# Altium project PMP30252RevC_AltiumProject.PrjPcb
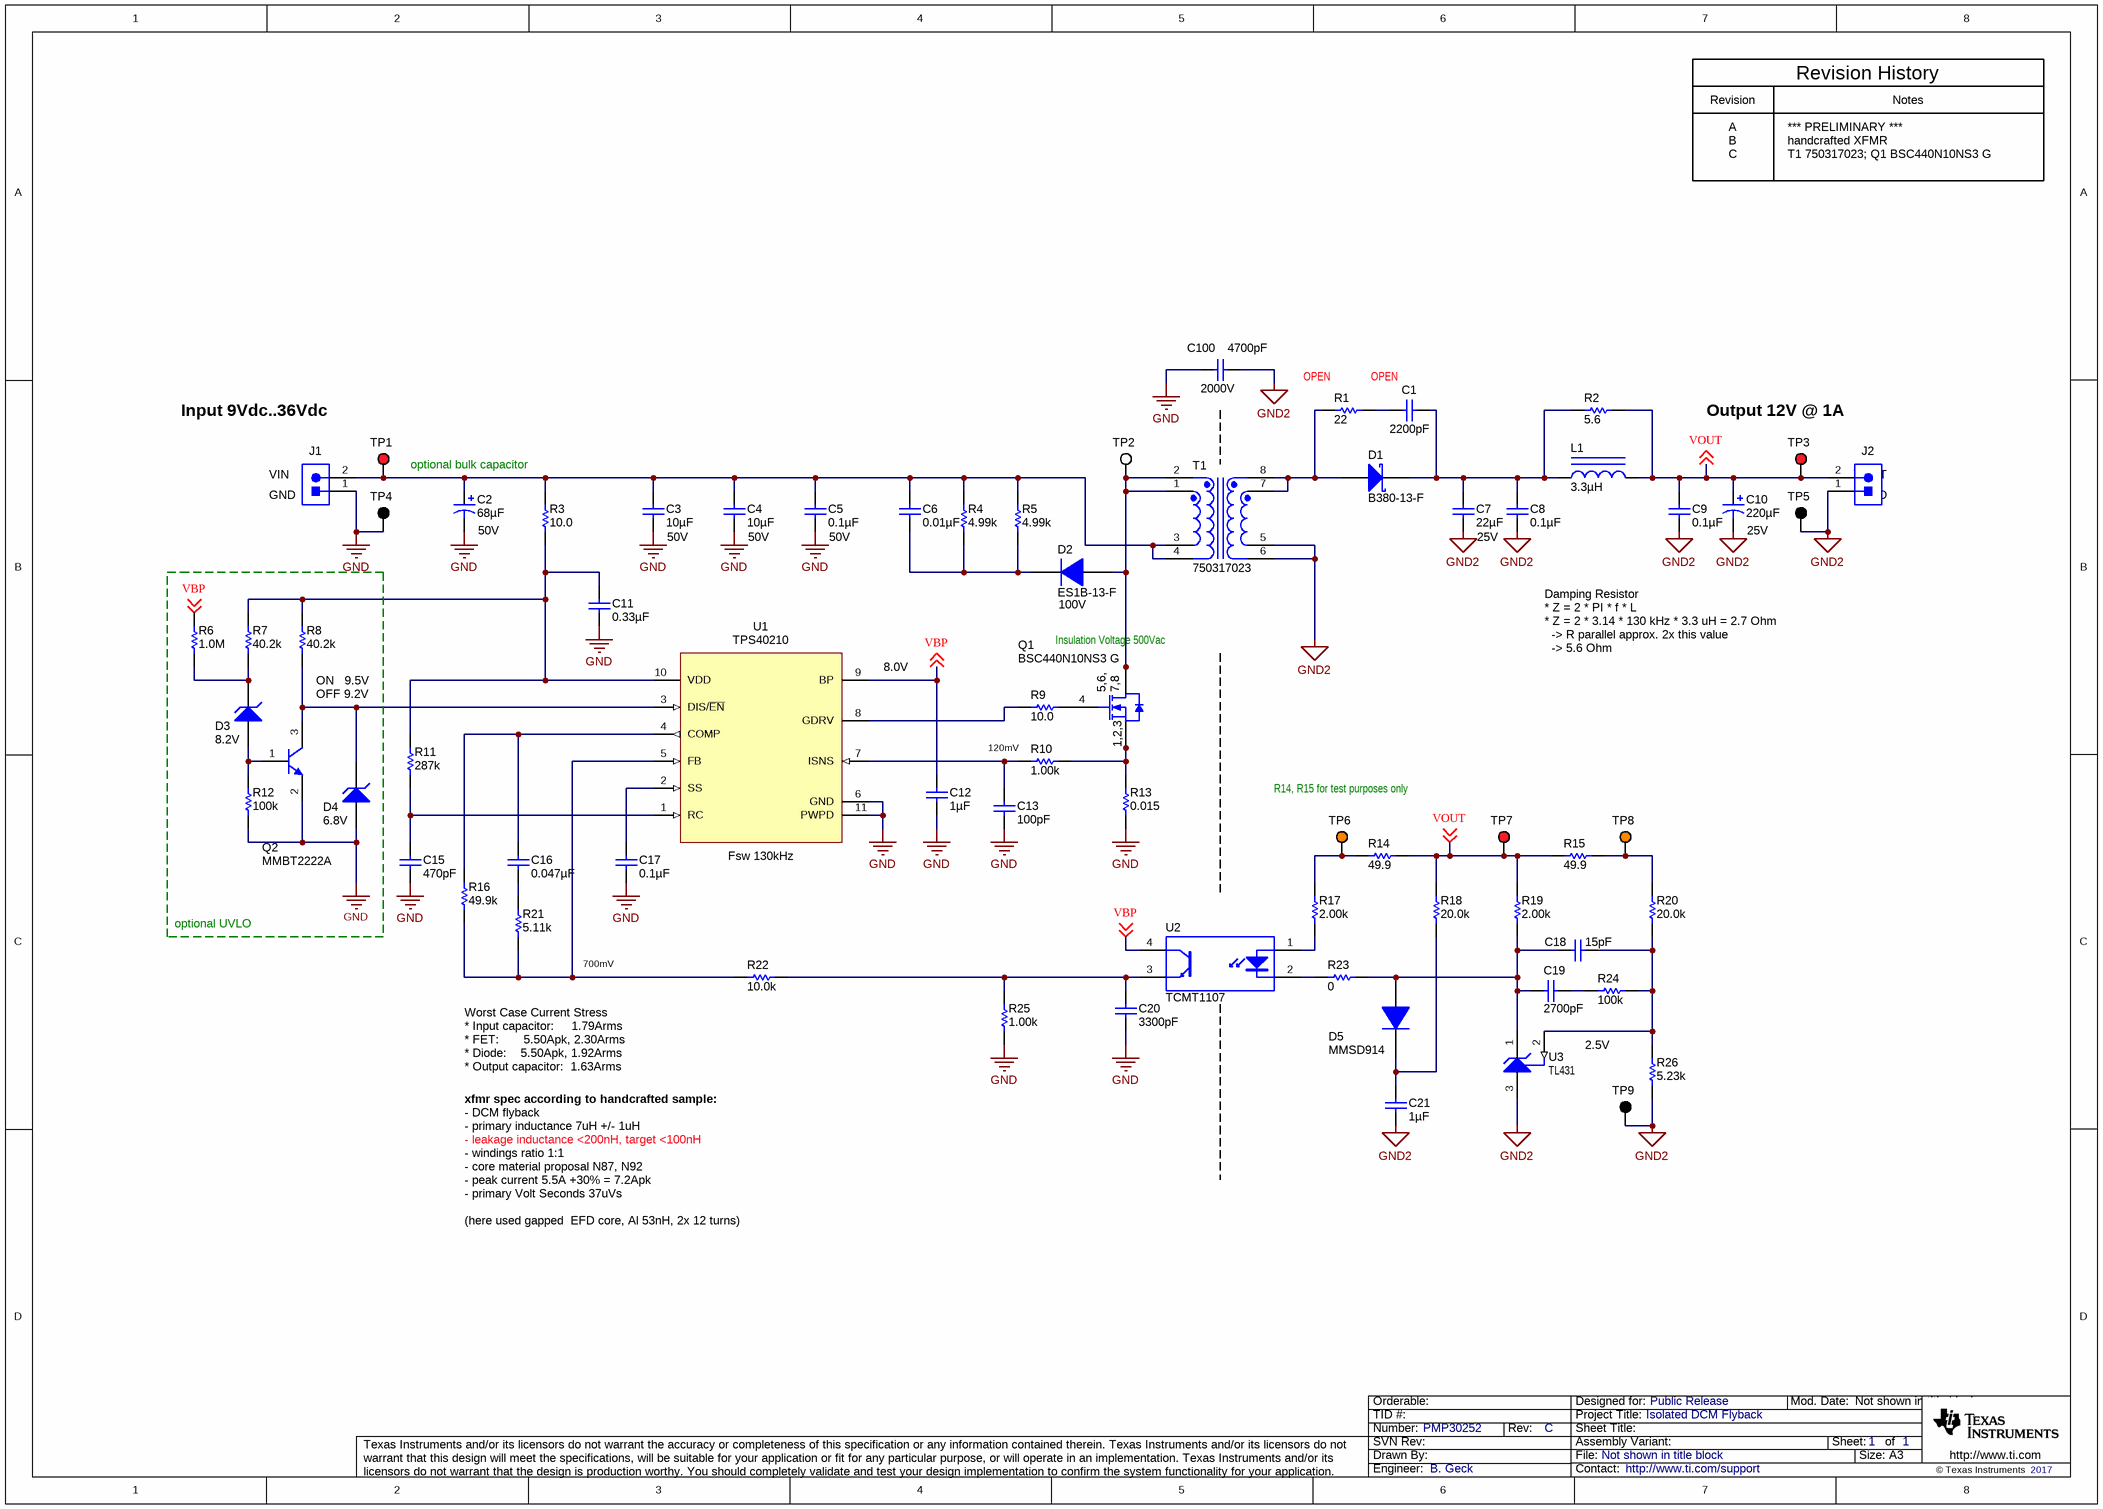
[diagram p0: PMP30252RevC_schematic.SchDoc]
CopyrightYear: 2017; PCB_Layout: B. Geck; PCB_Rev: A; PRJ_Customer: Public Release; PRJ_Engineer: B. Geck; PRJ_Number: PMP30252; PRJ_Title: Isolated DCM Flyback; SCH_Rev: C; TechSupport: http://www.ti.com/support
1 sheet, 70 parts. Net scope: global (net labels, ports and power ports of the same name join across sheets).
Board file: PMP30252RevA.PcbDoc

## Sheet PMP30252RevC_schematic.SchDoc
size A3; Date: Not shown in title block; ApprovedBy: Not shown in title block; CheckedBy: Not shown in title block; Author: Not shown in title block; CompanyName: Not shown in title block; Engineer: Not shown in title block; Organization: Not shown in title block; Address1: Not shown in title block; Address2: Not shown in title block; Address3: Not shown in title block; Address4: Not shown in title block; DocumentNumber: 1; Revision: Use project parameter SCH_Rev; SheetNumber: 1; SheetTotal: 1; PageSetup: Record=PageOptions¦CenterHorizontal=True¦CenterVertical=True¦PrintScale=0.68¦XCorrection=1.00¦YCorrection=1.00¦PrintKind=0¦BorderSize=5000000¦LeftOffset=0¦BottomOffset=0¦Orientation=2¦PaperLength=1000¦PaperWidth=1000¦Scale=100¦PaperSource=15¦PrintQuality=600¦MediaType=1¦DitherType=10¦PrintScaleMode=1¦PaperKind=A4¦PaperIndex=9

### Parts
C1  ValueDisplayed: 2200pF  [0603]  (hidden comment: GRM188R72A222KA01D)
C2  ValueDisplayed: 68µF  Value2: 50V  [SM_RADIAL_8MM]  (hidden comment: EEHZC1H680P)
C3  ValueDisplayed: 10µF  Value2: 50V  [1210_270]  (hidden comment: GRM32ER71H106KA12L)
C4  ValueDisplayed: 10µF  Value2: 50V  [1210_270]  (hidden comment: GRM32ER71H106KA12L)
C5  ValueDisplayed: 0.1µF  Value2: 50V  [0603]  (hidden comment: GCM188R71H104KA57D)
C6  ValueDisplayed: 0.01µF  [0805_HV]  (hidden comment: GRM21BR72A103MA01L)
C7  ValueDisplayed: 22µF  Value2: 25V  [1210_270]  (hidden comment: GRM32ER71E226KE15L)
C8  ValueDisplayed: 0.1µF  [0603]  (hidden comment: GCM188R71H104KA57D)
C9  ValueDisplayed: 0.1µF  [0603]  (hidden comment: GCM188R71H104KA57D)
C10  ValueDisplayed: 220µF  Value2: 25V  [SM_RADIAL_8MM]  (hidden comment: EEHZC1E221P)
C11  ValueDisplayed: 0.33µF  [0805_HV]  (hidden comment: GRM219R71H334KA88D)
C12  ValueDisplayed: 1µF  [0603]  (hidden comment: GRM188R71C105KA12D)
C13  ValueDisplayed: 100pF  [0603]  (hidden comment: GRM1885C1H101JA01D)
C15  ValueDisplayed: 470pF  [0603]  (hidden comment: GRM1885C1H471JA01D)
C16  ValueDisplayed: 0.047µF  [0603]  (hidden comment: GRM188R71E473KA01D)
C17  ValueDisplayed: 0.1µF  [0603]  (hidden comment: GCM188R71H104KA57D)
C18  ValueDisplayed: 15pF  [0603]  (hidden comment: GRM1885C1H150JA01D)
C19  ValueDisplayed: 2700pF  [0603]  (hidden comment: GRM188R71E272KA01D)
C20  ValueDisplayed: 3300pF  [0603]  (hidden comment: GRM188R71H332KA01D)
C21  ValueDisplayed: 1µF  [0603]  (hidden comment: GRM188R71C105KA12D)
C100  ValueDisplayed: 4700pF  Value2: 2000V  [1812]  (hidden comment: 1812GC472KA1)
D1  B380-13-F  [SMC]
D2  ES1B-13-F  value 100V  [SMA]
D3  value 8.2V  [SOD-323]  (hidden comment: MMSZ5237BS-7-F)
D4  value 6.8V  [sod-323]  (hidden comment: MMSZ5235BS-7-F)
D5  MMSD914  [SOD-123]
J1  ED555/2DS  [TERM_BLK_ED555-2DS]  (value not drawn)
J2  ED555/2DS  [TERM_BLK_ED555-2DS]  (value not drawn)
L1  ValueDisplayed: 3.3µH  [XFL4020]  (hidden comment: XFL4020-332MEB)
Q1  BSC440N10NS3 G  [PG-TDSON-8]
Q2  MMBT2222A  [SOT-23]
R1  ValueDisplayed: 22  [2010]  (hidden comment: CRCW201022R0JNEF)
R2  ValueDisplayed: 5.6  [1206]  (hidden comment: CRCW12065R60JNEA)
R3  ValueDisplayed: 10.0  [0603]  (hidden comment: CRCW060310R0FKEA)
R4  ValueDisplayed: 4.99k  [1206]  (hidden comment: CRCW12064K99FKEA)
R5  ValueDisplayed: 4.99k  [1206]  (hidden comment: CRCW12064K99FKEA)
R6  ValueDisplayed: 1.0M  [0603]  (hidden comment: CRCW06031M00JNEA)
R7  ValueDisplayed: 40.2k  [0603]  (hidden comment: CRCW060340K2FKEA)
R8  ValueDisplayed: 40.2k  [0603]  (hidden comment: CRCW060340K2FKEA)
R9  ValueDisplayed: 10.0  [0603]  (hidden comment: CRCW060310R0FKEA)
R10  ValueDisplayed: 1.00k  [0603]  (hidden comment: CRCW06031K00FKEA)
R11  ValueDisplayed: 287k  [0603]  (hidden comment: CRCW0603287KFKEA)
R12  value 100k  [0603]  (hidden comment: CRCW0603100KFKEA)
R13  ValueDisplayed: 0.015  [1206]  (hidden comment: WSLP1206R0150FEA)
R14  ValueDisplayed: 49.9  [0603]  (hidden comment: CRCW060349R9FKEA)
R15  ValueDisplayed: 49.9  [0603]  (hidden comment: CRCW060349R9FKEA)
R16  ValueDisplayed: 49.9k  [0603]  (hidden comment: CRCW060349K9FKEA)
R17  ValueDisplayed: 2.00k  [0603]  (hidden comment: CRCW06032K00FKEA)
R18  ValueDisplayed: 20.0k  [0603]  (hidden comment: CRCW060320K0FKEA)
R19  ValueDisplayed: 2.00k  [0603]  (hidden comment: CRCW06032K00FKEA)
R20  ValueDisplayed: 20.0k  [0603]  (hidden comment: CRCW060320K0FKEA)
R21  ValueDisplayed: 5.11k  [0603]  (hidden comment: CRCW06035K11FKEA)
R22  ValueDisplayed: 10.0k  [0603]  (hidden comment: CRCW060310K0FKEA)
R23  ValueDisplayed: 0  [0603]  (hidden comment: CRCW06030000Z0EA)
R24  ValueDisplayed: 100k  [0603]  (hidden comment: CRCW0603100KFKEA)
R25  ValueDisplayed: 1.00k  [0603]  (hidden comment: CRCW06031K00FKEA)
R26  ValueDisplayed: 5.23k  [0603]  (hidden comment: CRCW06035K23FKEA)
T1  750317023  [Wurth_070-5420]
TP1  5000  [Keystone5000]  (value not drawn)
TP2  5002  [Keystone5002]  (value not drawn)
TP3  5000  [Keystone5000]  (value not drawn)
TP4  5001  [Keystone5001]  (value not drawn)
TP5  5001  [Keystone5001]  (value not drawn)
TP6  5003  [Keystone5003]  (value not drawn)
TP7  5000  [Keystone5000]  (value not drawn)
TP8  5003  [Keystone5003]  (value not drawn)
TP9  5001  [Keystone5001]  (value not drawn)
U1  TPS40210  [DGQ0010D_N]
U2  TCMT1107  [SOP-4]
U3  TL431  [DBZ0003A_N]

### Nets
GND: C2.2(-) C3.2 C4.2 C5.2 C11.2 C12.2 C13.2 C15.2 C17.2 C20.2 C100.2 D4.2(A) J1.1 Q2.2(E) R12.1 R13.1 R25.1 TP4.1 U1.6(GND) U1.11(PWPD)
GND2: C7.2 C8.2 C9.2 C10.2(-) C21.2 C100.1 J2.1 R26.1 T1.5 T1.6 TP5.1 TP9.1 U3.3(ANODE)
VBP: C12.1 R6.2 U1.9(BP) U2.4(C) ; off-sheet VBP
VOUT: C9.1 C10.1(+) J2.2 L1.2 R2.2 R14.2 R15.1 R18.2 R19.2 TP3.1 TP7.1 ; off-sheet VOUT
NetC1_1: C1.1 C7.1 C8.1 D1.1(K) L1.1 R2.1
NetC1_2: C1.2 R1.2
NetC2_1: C2.1(+) C3.1 C4.1 C5.1 C6.1 J1.2 R3.2 R4.2 R5.2 T1.3 T1.4 TP1.1
NetC6_2: C6.2 D2.1(K) R4.1 R5.1
NetC11_1: C11.1 R3.1 R7.2 R8.2 R11.2 U1.10(VDD)
NetC13_1: C13.1 R10.1 U1.7(ISNS)
NetC15_1: C15.1 R11.1 U1.1(RC)
NetC16_1: C16.1 R16.2 U1.4(COMP)
NetC16_2: C16.2 R21.2
NetC17_1: C17.1 U1.2(SS)
NetC18_1: C18.1 R20.1 R24.2 R26.2 U3.2(REF)
NetC18_2: C18.2 C19.2 D5.2(A) R19.1 R23.1 U3.1(CATHODE)
NetC19_1: C19.1 R24.1
NetC20_1: C20.1 R22.2 R25.2 U2.3(E)
NetC21_1: C21.1 D5.1(K) R18.1
NetD1_2: D1.2(A) R1.1 T1.7 T1.8
NetD2_2: D2.2(A) Q1.5(D) Q1.6(D) Q1.7(D) Q1.8(D) Q1.9(D) T1.1 T1.2 TP2.1
NetD3_1: D3.1(K) R6.1 R7.1
NetD3_2: D3.2(A) Q2.1(B) R12.2
NetD4_1: D4.1(K) Q2.3(C) R8.1 U1.3(DIS/~{EN})
NetQ1_1: Q1.1(S) Q1.2(S) Q1.3(S) R10.2 R13.2
NetQ1_4: Q1.4(G) R9.2
NetR9_1: R9.1 U1.8(GDRV)
NetR14_1: R14.1 R17.2 TP6.1
NetR15_2: R15.2 R20.2 TP8.1
NetR16_1: R16.1 R21.1 R22.1 U1.5(FB)
NetR17_1: R17.1 U2.1(A)
NetR23_2: R23.2 U2.2(K)

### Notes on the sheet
- Revision
- Revision History
- Notes
- A
- B
- C
- *** PRELIMINARY ***
- handcrafted XFMR
- T1 750317023; Q1 BSC440N10NS3 G
- (near R1) OPEN
- (near C1) OPEN
- Input 9Vdc..36Vdc
- Output 12V @ 1A
- (near J1) VIN
- (near J1) GND
- optional bulk capacitor
- (near J2) VOUT
- (near J2) GND
- Insulation Voltage 500Vac
- Damping Resistor
  * Z = 2 * PI * f * L
  * Z = 2 * 3.14 * 130 kHz * 3.3 uH = 2.7 Ohm
  -> R parallel approx. 2x this value
  -> 5.6 Ohm
- (near R8) ON   9.5V
- OFF 9.2V
- (near U1) 8.0V
- (near R10) 120mV
- R14, R15 for test purposes only
- (near U1) Fsw 130kHz
- optional UVLO
- 700mV
- 2.5V
- Worst Case Current Stress
  * Input capacitor:     1.79Arms
  * FET:       5.50Apk, 2.30Arms
  * Diode:    5.50Apk, 1.92Arms
  * Output capacitor:  1.63Arms
- xfmr spec according to handcrafted sample:
- - DCM flyback
- - primary inductance 7uH +/- 1uH
- - windings ratio 1:1
- - leakage inductance <200nH, target <100nH
- - core material proposal N87, N92
- - peak current 5.5A +30% = 7.2Apk
- - primary Volt Seconds 37uVs
- (here used gapped  EFD core, Al 53nH, 2x 12 turns)

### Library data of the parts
C1 = GRM188R72A222KA01D: CAP, CERM, 2200 pF, 100 V, +/- 10%, X7R, 0603; Manufacturer: MuRata; Polarized: N; CompType: Capacitor; Value: 2200pF; U/M: EA; Cap_F: 0.0000000022; Tolerance_%: 10; Value1: Unknown; VDC_V: 100; Value2: 100V; TaMin_C: -55; TaMax_C: 125; SizeArea_mm2: 1.28; SizeAreaWB_mm2: 4.68; SizeX_mm: 1.6; SizeY_mm: 0.8; SizeZ_mm: 1; AEC Category: Q200
C2 = EEHZC1H680P: CAP, Polymer Hybrid, 68 µF, 50 V, +/- 20%, 30 ohm, 8x10 SMD; Manufacturer: Panasonic; Polarized: Y; CompType: Capacitor; Value: 68uF; U/M: EA; Cap_F: 0.000068; Tolerance_%: 20; Value1: 30 ohm; VDC_V: 50; ESR_ohm: 30; IRMS_A: 1.25; TaMin_C: -55; TaMax_C: 125; SizeAreaWB_mm2: 113.3; SizeArea_mm2: 74.7; SizeX_mm: 9; SizeY_mm: 8.3; SizeZ_mm: 10.2; AEC Category: Q200
C3 C4 = GRM32ER71H106KA12L: CAP, CERM, 10 µF, 50 V, +/- 10%, X7R, 1210; Manufacturer: MuRata; Polarized: N; CompType: Capacitor; Value: 10uF; U/M: EA; Cap_F: 0.00001; Tolerance_%: 10; Value1: Unknown; VDC_V: 50; TaMin_C: -55; TaMax_C: 125; Cap_Case: 1210; SizeArea_mm2: 8; SizeAreaWB_mm2: 14.7; SizeX_mm: 3.2; SizeY_mm: 2.5; SizeZ_mm: 2.7; AEC Category: Q200
C5 = GCM188R71H104KA57D: CAP, CERM, 0.1 µF, 50 V, +/- 10%, X7R, 0603; Manufacturer: MuRata; Polarized: N; CompType: Capacitor; Value: 0.1uF; U/M: EA; Cap_F: 0.0000001; Tolerance_%: 10; ESR_ohm: 0.02; Value1: 0.02 ohm; VDC_V: 50; IRMS_A: 1.84; TaMin_C: -55; TaMax_C: 125; AEC Category: Q200
C6 = GRM21BR72A103MA01L: CAP, CERM, 0.01 µF, 100 V, +/- 20%, X7R, 0805; Manufacturer: MuRata; Polarized: N; CompType: Capacitor; Value: 0.01uF; U/M: EA; Cap_F: 0.00000001; Tolerance_%: 20; Value1: Unknown; VDC_V: 100; Value2: 100V; TaMin_C: -55; TaMax_C: 125; Cap_Case: 0805; SizeArea_mm2: 2.5; SizeAreaWB_mm2: 6.75; SizeX_mm: 2; SizeY_mm: 1.25; SizeZ_mm: 1.45; AEC Category: Q200
C7 = GRM32ER71E226KE15L: CAP, CERM, 22 µF, 25 V, +/- 10%, X7R, 1210; Manufacturer: MuRata; Polarized: N; CompType: Capacitor; Value: 22uF; U/M: EA; Cap_F: 0.000022; Tolerance_%: 10; Value1: Unknown; VDC_V: 25; TaMin_C: -55; TaMax_C: 125; Cap_Case: 1210; SizeArea_mm2: 8; SizeAreaWB_mm2: 14.7; SizeX_mm: 3.2; SizeY_mm: 2.5; SizeZ_mm: 2.7; AEC Category: Q200
C8 C9 C17 = GCM188R71H104KA57D: CAP, CERM, 0.1 µF, 50 V, +/- 10%, X7R, 0603; Manufacturer: MuRata; Polarized: N; CompType: Capacitor; Value: 0.1uF; U/M: EA; Cap_F: 0.0000001; Tolerance_%: 10; ESR_ohm: 0.02; Value1: 0.02 ohm; VDC_V: 50; Value2: 50V; IRMS_A: 1.84; TaMin_C: -55; TaMax_C: 125; AEC Category: Q200
C10 = EEHZC1E221P: CAP, Polymer Hybrid, 220 µF, 25 V, +/- 20%, 27 ohm, 8x10 SMD; Manufacturer: Panasonic; Polarized: Y; CompType: Capacitor; Value: 220uF; U/M: EA; Cap_F: 0.00022; Tolerance_%: 20; Value1: 27 ohm; VDC_V: 25; ESR_ohm: 27; IRMS_A: 1.6; TaMin_C: -55; TaMax_C: 125; SizeAreaWB_mm2: 113.3; SizeArea_mm2: 74.7; SizeX_mm: 9; SizeY_mm: 8.3; SizeZ_mm: 10.2; AEC Category: Q200
C11 = GRM219R71H334KA88D: CAP, CERM, 0.33 µF, 50 V, +/- 10%, X7R, 0805; Manufacturer: MuRata; Polarized: N; CompType: Capacitor; Value: 0.33uF; U/M: EA; Cap_F: 0.00000033; Tolerance_%: 10; Value1: Unknown; VDC_V: 50; Value2: 50V; TaMin_C: -55; TaMax_C: 125; Cap_Case: 0805; AEC Category: Q200
C12 C21 = GRM188R71C105KA12D: CAP, CERM, 1 µF, 16 V, +/- 10%, X7R, 0603; Manufacturer: MuRata; Polarized: N; CompType: Capacitor; Value: 1uF; U/M: EA; Cap_F: 0.000001; Tolerance_%: 10; ESR_ohm: 0.011; Value1: 0.011 ohm; VDC_V: 16; Value2: 16V; TaMin_C: -55; TaMax_C: 125; AEC Category: Q200
C13 = GRM1885C1H101JA01D: CAP, CERM, 100 pF, 50 V, +/- 5%, C0G/NP0, 0603; Manufacturer: MuRata; Polarized: N; CompType: Capacitor; Value: 100pF; U/M: EA; Cap_F: 0.0000000001; Tolerance_%: 5; Value1: Unknown; VDC_V: 50; Value2: 50V; TaMin_C: -55; TaMax_C: 125; SizeArea_mm2: 1.28; SizeAreaWB_mm2: 4.68; SizeX_mm: 1.6; SizeY_mm: 0.8; SizeZ_mm: 1; AEC Category: Q200
C15 = GRM1885C1H471JA01D: CAP, CERM, 470 pF, 50 V, +/- 5%, C0G/NP0, 0603; Manufacturer: MuRata; Polarized: N; CompType: Capacitor; Value: 470pF; U/M: EA; Cap_F: 0.00000000047; Tolerance_%: 5; Value1: Unknown; VDC_V: 50; Value2: 50V; TaMin_C: -55; TaMax_C: 125; SizeArea_mm2: 1.28; SizeAreaWB_mm2: 4.68; SizeX_mm: 1.6; SizeY_mm: 0.8; SizeZ_mm: 1; AEC Category: Q200
C16 = GRM188R71E473KA01D: CAP, CERM, 0.047 µF, 25 V, +/- 10%, X7R, 0603; Manufacturer: MuRata; Polarized: N; CompType: Capacitor; Value: 0.047uF; U/M: EA; Cap_F: 0.000000047; Tolerance_%: 10; Value1: Unknown; VDC_V: 25; Value2: 25V; TaMin_C: -55; TaMax_C: 125; SizeArea_mm2: 1.28; SizeAreaWB_mm2: 4.68; SizeX_mm: 1.6; SizeY_mm: 0.8; SizeZ_mm: 1; AEC Category: Q200
C18 = GRM1885C1H150JA01D: CAP, CERM, 15 pF, 50 V, +/- 5%, C0G/NP0, 0603; Manufacturer: MuRata; Polarized: N; CompType: Capacitor; Value: 15pF; U/M: EA; Cap_F: 0.000000000015; Tolerance_%: 5; Value1: Unknown; VDC_V: 50; Value2: 50V; TaMin_C: -55; TaMax_C: 125; SizeArea_mm2: 1.28; SizeAreaWB_mm2: 4.68; SizeX_mm: 1.6; SizeY_mm: 0.8; SizeZ_mm: 1; AEC Category: Q200
C19 = GRM188R71E272KA01D: CAP, CERM, 2700 pF, 25 V, +/- 10%, X7R, 0603; Manufacturer: MuRata; Polarized: N; CompType: Capacitor; Value: 2700pF; U/M: EA; Cap_F: 0.0000000027; Tolerance_%: 10; Value1: Unknown; VDC_V: 25; Value2: 25V; TaMin_C: -55; TaMax_C: 125; SizeArea_mm2: 1.28; SizeAreaWB_mm2: 4.68; SizeX_mm: 1.6; SizeY_mm: 0.8; SizeZ_mm: 1; AEC Category: Q200
C20 = GRM188R71H332KA01D: CAP, CERM, 3300 pF, 50 V, +/- 10%, X7R, 0603; Manufacturer: MuRata; Polarized: N; CompType: Capacitor; Value: 3300pF; U/M: EA; Cap_F: 0.0000000033; Tolerance_%: 10; Value1: Unknown; VDC_V: 50; Value2: 50V; TaMin_C: -55; TaMax_C: 125; SizeArea_mm2: 1.28; SizeAreaWB_mm2: 4.68; SizeX_mm: 1.6; SizeY_mm: 0.8; SizeZ_mm: 1; AEC Category: Q200
C100 = 1812GC472KA1: CAP, CERM, 4700 pF, 2000 V, +/- 10%, X7R, 1812; Manufacturer: AVX; Polarized: N; CompType: Capacitor; Value: 4700pF; U/M: EA; Cap_F: 0.0000000047; Tolerance_%: 10; Value1: Unknown; VDC_V: 2000; TaMin_C: -55; TaMax_C: 125; SizeArea_mm2: 14.4; SizeAreaWB_mm2: 23.1; SizeX_mm: 4.5; SizeY_mm: 3.2; SizeZ_mm: 1.35; AEC Category: Q200
D1 = B380-13-F: Diode, Schottky, 80 V, 3 A, SMC; Manufacturer: Diodes Inc.; U/M: EA; Vf_V: 0.79; Value: 80V; Value1: 3A; Value2: 0.79V; Io_A: 3; Vr_V: 80; TJmax_C: 125; RJC_CperW: 10; SizeAreaWB_mm2: 83.2686; SizeArea_mm2: 50.5686; SizeX_mm: 8.13; SizeY_mm: 6.22; SizeZ_mm: 2.6; AEC Category: Q101
D2 = ES1B-13-F: Diode, Superfast Rectifier, 100 V, 1 A, SMA; Manufacturer: Diodes Inc.; U/M: EA; Vf_V: 0.92; Value1: 1A; Value2: 0.92V; Io_A: 1; Vr_V: 100; TJmax_C: 150; RJC_CperW: 25; SizeAreaWB_mm2: 37.3428; SizeArea_mm2: 16.3228; SizeX_mm: 5.59; SizeY_mm: 2.92; SizeZ_mm: 2.87; AEC Category: Q101
D3 = MMSZ5237BS-7-F: Diode, Zener, 8.2 V, 200 mW, SOD-323; Manufacturer: Diodes Inc.; SymbolCreator: a0412235; U/M: EA; Power_W: 0.2; Vz_V: 8.2; Value1: 0.2W; RJA_CperW: 350; SizeAreaWB_mm2: 8.695; SizeArea_mm2: 3.645; SizeX_mm: 2.7; SizeY_mm: 1.35; SizeZ_mm: 1; AEC Category: Q101
D4 = MMSZ5235BS-7-F: Diode, Zener, 6.8V, 200mW, SOD-323; Manufacturer: Diodes Inc.; SymbolCreator: a0412235; U/M: EA; Power_W: 0.2; Vz_V: 6.8; Value1: 0.2W; RJA_CperW: 350
D5 = MMSD914T1G: Diode, Switching, 100 V, 0.2 A, SOD-123; Manufacturer: ON Semiconductor; U/M: EA; Value: 100V; Value1: 0.2A; Io_A: 0.2; Vr_V: 100; TJmax_C: 150; SizeAreaWB_mm2: 13.095; SizeArea_mm2: 6.545; SizeX_mm: 3.85; SizeY_mm: 1.7; SizeZ_mm: 1.35; AEC Category: Q101
J1 J2 = ED555/2DS: Terminal Block, 6A, 3.5mm Pitch, 2-Pos, TH; Manufacturer: On-Shore Technology; SymbolCreator: a0412235; CompType: Connector; U/M: EA
L1 = XFL4020-332MEB: Inductor, Shielded, Composite, 3.3 µH, 2.9 A, 0.03 ohm, SMD; Manufacturer: Coilcraft; Value: 3.3uH; Ind_H: 3.3E-6; Imax_A: 2.9; Irms: 5.2A @ 40C rise; Isat: 2.9A @ 30% inductance drop; DCR_ohm: 0.03; Value2: 2.9A; SizeAreaWB_mm2: 25; SizeArea_mm2: 16; SizeX_mm: 4; SizeZ_mm: 2.15; AEC Category: Q200
Q1 = BSC340N08NS3 G: MOSFET, N-CH, 100 V, PG-TDSON-8; Manufacturer: Infineon Technologies; Alternate Manufacturer: None; U/M: EA; ChType: N; Value: 100V; VdsMax_V: 100; Value1: 0.044 ohm; Rdson45_ohm: 0.065; Value2: 10.8 nC; QgTyp_nC: 6.8; Vgs_V: 20; IdsMax_A: 23; SizeAreaWB_mm2: 55.131; SizeArea_mm2: 29.351; SizeX_mm: 5.99; SizeY_mm: 4.9; SizeZ_mm: 1.12; AEC Category: Q101
Q2 = MMBT2222A, Fairchild Semiconductor: Transistor, NPN, 40V, 0.15A, SOT-23; CompType: BJT; PNP: 0; NPN: 1; Vceo_V: 40; Vcesat1_V: 0.3; Value: 0.3V; IcRated_A: 0.15; HfeMax: 300; TaMin_C: -55; TaMax_C: 150; U/M: EA
R1 = CRCW201022R0JNEF: RES, 22, 5%, 0.75 W, AEC-Q200 Grade 0, 2010; Manufacturer: Vishay-Dale; CompType: Resistor; Value: 22; Value_Code: 22R0; Tolerance_%: 5; Power_W: 0.75; Value2: 0.75W; VDC_V: 400; TempCo: 200 ppm/C; SizeArea_mm2: 12.5; SizeY_mm: 2.5; SizeZ_mm: 1.66; EIA_Code: E24; U/M: EA; AEC Category: Q200; AEC Qualified: Y; AEC Grade: 0
R2 = CRCW12065R60JNEA: RES, 5.6, 5%, 0.25 W, 1206; Manufacturer: Vishay-Dale; CompType: Resistor; Value: 5.6; Value_Code: 5R60; Tolerance_%: 5; Power_W: 0.25; Value2: 0.25W; VDC_V: 200; TempCo: 200 ppm/C; SizeArea_mm2: 5.12; SizeX_mm: 3.2; SizeY_mm: 1.6; SizeZ_mm: 1.35; EIA_Code: E24; U/M: EA; AEC Category: Q200
R3 R9 = CRCW060310R0FKEA: RES, 10.0, 1%, 0.1 W, 0603; Manufacturer: Vishay-Dale; CompType: Resistor; Value: 10.0; Res_ohm: 10; Value_Code: 10R0; Tolerance_%: 1; Power_W: 0.1; Value2: 0.1W; VDC_V: 75; TempCo: 100 ppm/C; SizeArea_mm2: 1.28; SizeX_mm: 1.6; SizeY_mm: 0.8; EIA_Code: E96; U/M: EA; AEC Category: Q200
R4 R5 = CRCW12064K99FKEA: RES, 4.99 k, 1%, 0.25 W, 1206; Manufacturer: Vishay-Dale; CompType: Resistor; Value: 4.99k; Res_ohm: 4990; Value_Code: 4k99; Tolerance_%: 1; Power_W: 0.25; Value2: 0.25W; VDC_V: 200; TempCo: 100 ppm/C; SizeArea_mm2: 5.12; SizeX_mm: 3.2; SizeY_mm: 1.6; SizeZ_mm: 1.35; EIA_Code: E96; U/M: EA; AEC Category: Q200
R6 = CRCW06031M00JNEA: RES, 1.0 M, 5%, 0.1 W, 0603; Manufacturer: Vishay-Dale; CompType: Resistor; Value: 1.0Meg; Res_ohm: 1000000; Value_Code: 1M00; Tolerance_%: 5; Power_W: 0.1; Value2: 0.1W; VDC_V: 75; TempCo: 200 ppm/C; SizeArea_mm2: 1.28; SizeX_mm: 1.6; SizeY_mm: 0.8; SizeZ_mm: 1; EIA_Code: E24; U/M: EA; AEC Category: Q200
R7 R8 = CRCW060340K2FKEA: RES, 40.2 k, 1%, 0.1 W, 0603; Manufacturer: Vishay-Dale; CompType: Resistor; Value: 40.2k; Res_ohm: 40200; Value_Code: 40k2; Tolerance_%: 1; Power_W: 0.1; Value2: 0.1W; VDC_V: 75; TempCo: 100 ppm/C; SizeArea_mm2: 1.28; SizeX_mm: 1.6; SizeY_mm: 0.8; EIA_Code: E96; U/M: EA; AEC Category: Q200
R10 = CRCW06031K00FKEA: RES, 1.00 k, 1%, 0.1 W, 0603; Manufacturer: Vishay-Dale; CompType: Resistor; Value: 1.00k; Res_ohm: 1000; Value_Code: 1k00; Tolerance_%: 1; Power_W: 0.1; Value2: 0.1W; VDC_V: 75; TempCo: 100 ppm/C; EIA_Code: E96; U/M: EA
R11 = CRCW0603287KFKEA: RES, 287 k, 1%, 0.1 W, 0603; Manufacturer: Vishay-Dale; CompType: Resistor; Value: 287k; Res_ohm: 287000; Tolerance_%: 1; Power_W: 0.1; Value2: 0.1W; VDC_V: 75; TempCo: 100 ppm/C; SizeArea_mm2: 1.28; SizeX_mm: 1.6; SizeY_mm: 0.8; EIA_Code: E96; U/M: EA; AEC Category: Q200
R12 = CRCW0603100KFKEA: RES, 100k ohm, 1%, 0.1W, 0603; Manufacturer: Vishay-Dale; CompType: Resistor; Res_ohm: 100000; Tolerance_%: 1; Power_W: 0.1; VDC_V: 75; TempCo: 100 ppm/C; EIA_Code: E96; U/M: EA
R13 = WSLP1206R0150FEA: RES, 0.015, 1%, 1 W, 1206; Manufacturer: Vishay-Dale; CompType: Resistor; Value: 0.015; Value_Code: R015; Tolerance_%: 1; Value2: 1W; TempCo: 75 ppm/C; SizeArea_mm2: 5.12; SizeX_mm: 3.2; SizeY_mm: 1.6; SizeZ_mm: 1.35; EIA_Code: E96; U/M: EA; AEC Category: Q200
R14 R15 = CRCW060349R9FKEA: RES, 49.9, 1%, 0.1 W, 0603; Manufacturer: Vishay-Dale; CompType: Resistor; Value: 49.9; Value_Code: 49R9; Tolerance_%: 1; Power_W: 0.1; Value2: 0.1W; VDC_V: 75; TempCo: 100 ppm/C; SizeArea_mm2: 1.28; SizeX_mm: 1.6; SizeY_mm: 0.8; EIA_Code: E96; U/M: EA; AEC Category: Q200
R16 = CRCW060349K9FKEA: RES, 49.9 k, 1%, 0.1 W, 0603; Manufacturer: Vishay-Dale; CompType: Resistor; Value: 49.9k; Res_ohm: 49900; Value_Code: 49k9; Tolerance_%: 1; Power_W: 0.1; Value2: 0.1W; VDC_V: 75; TempCo: 100 ppm/C; SizeArea_mm2: 1.28; SizeX_mm: 1.6; SizeY_mm: 0.8; EIA_Code: E96; U/M: EA; AEC Category: Q200
R17 R19 = CRCW06032K00FKEA: RES, 2.00 k, 1%, 0.1 W, 0603; Manufacturer: Vishay-Dale; CompType: Resistor; Value: 2.00k; Res_ohm: 2000; Value_Code: 2k00; Tolerance_%: 1; Power_W: 0.1; Value2: 0.1W; VDC_V: 75; TempCo: 100 ppm/C; SizeArea_mm2: 1.28; SizeX_mm: 1.6; SizeY_mm: 0.8; EIA_Code: E96; U/M: EA; AEC Category: Q200
R18 R20 = CRCW060320K0FKEA: RES, 20.0 k, 1%, 0.1 W, 0603; Manufacturer: Vishay-Dale; CompType: Resistor; Value: 20.0k; Res_ohm: 20000; Value_Code: 20k0; Tolerance_%: 1; Power_W: 0.1; Value2: 0.1W; VDC_V: 75; TempCo: 100 ppm/C; SizeArea_mm2: 1.28; SizeX_mm: 1.6; SizeY_mm: 0.8; EIA_Code: E96; U/M: EA; AEC Category: Q200
R21 = CRCW06035K11FKEA: RES, 5.11 k, 1%, 0.1 W, 0603; Manufacturer: Vishay-Dale; CompType: Resistor; Value: 5.11k; Res_ohm: 5110; Value_Code: 5k11; Tolerance_%: 1; Power_W: 0.1; Value2: 0.1W; VDC_V: 75; TempCo: 100 ppm/C; SizeArea_mm2: 1.28; SizeX_mm: 1.6; SizeY_mm: 0.8; EIA_Code: E96; U/M: EA; AEC Category: Q200
R22 = CRCW060310K0FKEA: RES, 10.0 k, 1%, 0.1 W, 0603; Manufacturer: Vishay-Dale; CompType: Resistor; Value: 10.0k; Res_ohm: 10000; Value_Code: 10k0; Tolerance_%: 1; Power_W: 0.1; Value2: 0.1W; VDC_V: 75; TempCo: 100 ppm/C; SizeArea_mm2: 1.28; SizeX_mm: 1.6; SizeY_mm: 0.8; EIA_Code: E96; U/M: EA; AEC Category: Q200
R23 = CRCW06030000Z0EA: RES, 0, 5%, 0.1 W, 0603; Manufacturer: Vishay-Dale; CompType: Resistor; Value: 0; Value_Code: 0000; Tolerance_%: 5; Power_W: 0.1; Value2: 0.1W; VDC_V: 75; TempCo: 200 ppm/C; SizeArea_mm2: 1.28; SizeX_mm: 1.6; SizeY_mm: 0.8; SizeZ_mm: 1; EIA_Code: E24; U/M: EA; AEC Category: Q200
R24 = CRCW0603100KFKEA: RES, 100 k, 1%, 0.1 W, 0603; Manufacturer: Vishay-Dale; CompType: Resistor; Value: 100k; Res_ohm: 100000; Tolerance_%: 1; Power_W: 0.1; Value2: 0.1W; VDC_V: 75; TempCo: 100 ppm/C; SizeArea_mm2: 1.28; SizeX_mm: 1.6; SizeY_mm: 0.8; EIA_Code: E96; U/M: EA; AEC Category: Q200
R25 = CRCW06031K00FKEA: RES, 1.00 k, 1%, 0.1 W, 0603; Manufacturer: Vishay-Dale; CompType: Resistor; Value: 1.00k; Res_ohm: 1000; Value_Code: 1k00; Tolerance_%: 1; Power_W: 0.1; Value2: 0.1W; VDC_V: 75; TempCo: 100 ppm/C; SizeArea_mm2: 1.28; SizeX_mm: 1.6; SizeY_mm: 0.8; EIA_Code: E96; U/M: EA; AEC Category: Q200
R26 = CRCW06035K23FKEA: RES, 5.23 k, 1%, 0.1 W, 0603; Manufacturer: Vishay-Dale; CompType: Resistor; Value: 5.23k; Res_ohm: 5230; Value_Code: 5k23; Tolerance_%: 1; Power_W: 0.1; Value2: 0.1W; VDC_V: 75; TempCo: 100 ppm/C; SizeArea_mm2: 1.28; SizeX_mm: 1.6; SizeY_mm: 0.8; EIA_Code: E96; U/M: EA; AEC Category: Q200
T1 = CMP-0077306-1: Transformer, 7 uH, TH; Manufacturer: Wurth Elektronik; AEC Qualified: N; Lp: 7.0; AEC Category: Q200; Value: 7uH; Ind_H: 7µH; Ns1toNp: 1.0; LeakageInd_H: 100nH; Rsec1_ohm: 0.021; DCR_ohm: 0.014
TP1 TP3 TP7 = 5000: Test Point, Miniature, Red, TH; Manufacturer: Keystone; CompType: Test Point Loop; U/M: EA
TP2 = 5002: Test Point, Miniature, White, TH; Manufacturer: Keystone; CompType: Test Point Loop; ContactFinish: Silver
TP4 TP5 TP9 = 5001: Test Point, Miniature, Black, TH; Manufacturer: Keystone; CompType: Test Point Loop; U/M: EA
TP6 TP8 = 5003: Test Point, Miniature, Orange, TH; Manufacturer: Keystone; CompType: Test Point Loop; ContactFinish: Silver
U1 = TPS40210QDGQRQ1: 4.5-V TO 52-V INPUT CURRENT MODE BOOST CONTROLLER, DGQ0010D; Manufacturer: Texas Instruments; SymbolCreator: a0412235; CompType: IC; U/M: EA
U2 = TCMT1107: Optocoupler, 3.75 kV, 80-160% CTR, SMT; Manufacturer: Vishay-Semiconductor; CTR (Min): 80%; CTR (Max): 160%; Voltage_Isolation_Vrms: 3750V; SizeAreaWB_mm2: 43.65; SizeArea_mm2: 19.95; SizeX_mm: 7; SizeY_mm: 2.85; SizeZ_mm: 2.3
U3 = TL431AIDBZR: Adjustable Precision Shunt Regulator, 34 ppm / degC, 100 mA, -40 to 85 degC, 3-pin SOT-23 (DBZ), Green (RoHS & no Sb/Br); Manufacturer: Texas Instruments; Alternate PartNumber: Equivalent; Initial Accuracy @ 25/deg C(%): 1; Iout/Iz(Max)(mA): 100; Min Iz for Regulation(uA): 600; Rating: Catalog; SubFamily: Shunt Voltage Reference; Temp Coeff(Max)(ppm/ degree C): 92; Temp Coeff(Typ)(ppm/ degree C): 34; VO Adj(Max)(V): 36; VO Adj(Min)(V): 2.495

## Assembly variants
001: all parts fitted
